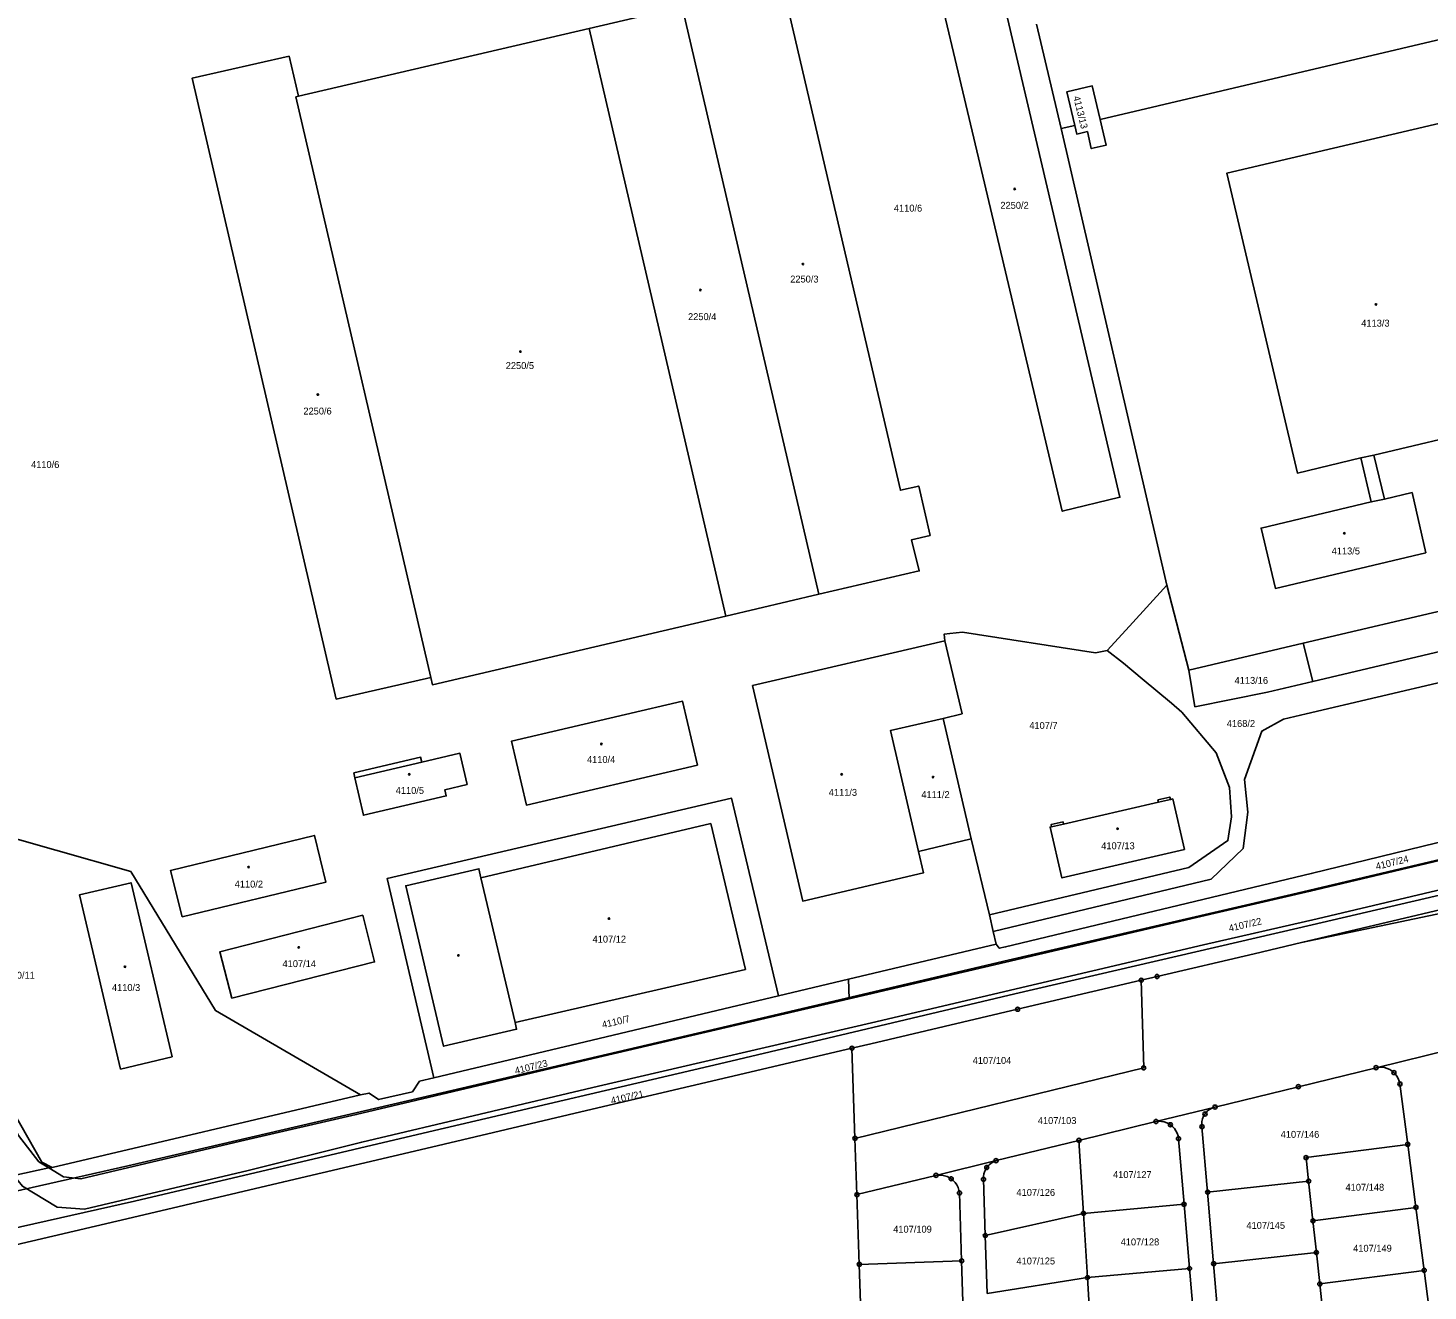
# Model space of a CAD drawing. Extents: x -733394 to -722299, y -1082822 to -1075049.
# Drawn here: x -728180.6 to -727836.8, y -1080927.6 to -1080617.4 of the extents above; entities that cross this region are included whole.
import ezdxf

# ---------------------------------------------------------------- set-up
doc = ezdxf.new("R2010")
doc.units = 0
for name, color, linetype in [('Hranice parcel', 7, 'Continuous'), ('Parcelní čísla', 7, 'Continuous'), ('Vnitřní kresba', 7, 'Continuous'), ('Značky bodu BP', 7, 'Continuous'), ('Značky budov', 7, 'Continuous')]:
    doc.layers.add(name, color=color, linetype=linetype)

msp = doc.modelspace()

# ---------------------------------------------------------------- linework, layer by layer
at = {"layer": 'Hranice parcel'}
for p, q in [((-728019.93, -1080612.18), (-728042.79, -1080617.52)), ((-728019.93, -1080612.18), (-727986.32, -1080756.51)), ((-727932.89, -1080616.46), (-727926.83, -1080642.13)), ((-727917.27, -1080639.88), (-727812.13, -1080615.13)), ((-728042.79, -1080617.52), (-728114.15, -1080634.19)), ((-728042.79, -1080617.52), (-728009.18, -1080761.86)), ((-727926.83, -1080642.13), (-727923.52, -1080641.35)), ((-727926.83, -1080642.13), (-727900.86, -1080754.24)), ((-727853.28, -1080722.98), (-727850.06, -1080722.32)), ((-727781.26, -1080748.19), (-727867.44, -1080768.52)), ((-727900.86, -1080754.24), (-727895.51, -1080775.14)), ((-728009.18, -1080761.86), (-727986.32, -1080756.51)), ((-727865.08, -1080777.91), (-727767.33, -1080754.84)), ((-727867.44, -1080768.52), (-727895.51, -1080775.14)), ((-727865.08, -1080777.91), (-727867.44, -1080768.52)), ((-727955.78, -1080786.98), (-727948.92, -1080816.58)), ((-727867.8, -1080842.03), (-727745.31, -1080813.05)), ((-727961.84, -1080819.67), (-727948.92, -1080816.58)), ((-727948.92, -1080816.58), (-727944.46, -1080835.28)), ((-727944.46, -1080835.28), (-727943.51, -1080839.35)), ((-727943.51, -1080839.35), (-727942.78, -1080842.47)), ((-727942.78, -1080842.47), (-727979.06, -1080851.08)), ((-727979.06, -1080851.08), (-727996.25, -1080855.17)), ((-727978.89, -1080855.88), (-727979.06, -1080851.08)), ((-727996.25, -1080855.17), (-728080.91, -1080875.25)), ((-727977.47, -1080890.16), (-727978.23, -1080868)), ((-727830.91, -1080868.23), (-727849.52, -1080872.78)), ((-727843.66, -1080876.78), (-727841.73, -1080891.63)), ((-728098.92, -1080879.42), (-728174.61, -1080897.33)), ((-727889.05, -1080882.45), (-727903.58, -1080886.01)), ((-727922.47, -1080890.63), (-727903.58, -1080886.01)), ((-727890.89, -1080903.36), (-727892.26, -1080887.28)), ((-727977, -1080903.97), (-727977.47, -1080890.16)), ((-727942.84, -1080895.62), (-727922.47, -1080890.63)), ((-727921.36, -1080908.58), (-727922.47, -1080890.63)), ((-727898.03, -1080890.23), (-727896.66, -1080906.34)), ((-727841.73, -1080891.63), (-727839.72, -1080907.1)), ((-728184, -1080899.3), (-728175.41, -1080897.39)), ((-728175.41, -1080897.39), (-728174.61, -1080897.33)), ((-727942.84, -1080895.62), (-727957.6, -1080899.23)), ((-727977, -1080903.97), (-727957.6, -1080899.23)), ((-727945.48, -1080913.99), (-727945.91, -1080900.2)), ((-727866.07, -1080900.66), (-727890.89, -1080903.36)), ((-727865.02, -1080910.4), (-727866.07, -1080900.66)), ((-727976.41, -1080921.1), (-727977, -1080903.97)), ((-727951.81, -1080903.56), (-727951.28, -1080920.23)), ((-727889.4, -1080920.93), (-727890.89, -1080903.36)), ((-727921.36, -1080908.58), (-727945.48, -1080913.99)), ((-727921.36, -1080908.58), (-727896.66, -1080906.34)), ((-727920.39, -1080924.33), (-727921.36, -1080908.58)), ((-727896.66, -1080906.34), (-727895.32, -1080922.11)), ((-727865.02, -1080910.4), (-727839.72, -1080907.1)), ((-727839.72, -1080907.1), (-727837.7, -1080922.57)), ((-727864.17, -1080918.18), (-727865.02, -1080910.4)), ((-727945.02, -1080928.26), (-727945.48, -1080913.99)), ((-727864.17, -1080918.18), (-727889.4, -1080920.93)), ((-727863.33, -1080925.91), (-727864.17, -1080918.18)), ((-727976.41, -1080921.1), (-727951.28, -1080920.23)), ((-727975.83, -1080938.05), (-727976.41, -1080921.1)), ((-727951.28, -1080920.23), (-727950.74, -1080937.18)), ((-727920.39, -1080924.33), (-727895.32, -1080922.11)), ((-727895.32, -1080922.11), (-727893.98, -1080937.88)), ((-727887.91, -1080938.51), (-727889.4, -1080920.93)), ((-727863.33, -1080925.91), (-727837.7, -1080922.57)), ((-727837.7, -1080922.57), (-727835.69, -1080938.04)), ((-727920.39, -1080924.33), (-727945.02, -1080928.26)), ((-727919.41, -1080940.12), (-727920.39, -1080924.33)), ((-727862.26, -1080935.72), (-727863.33, -1080925.91))]:
    msp.add_line(p, q, dxfattribs=at)
for points in [[(-727947.15, -1080584.43), (-727947.53, -1080584.52), (-727961.69, -1080587.81), (-727946.42, -1080652.42), (-727926.58, -1080736.12), (-727912.4, -1080732.68), (-727933.04, -1080644.64), (-727945.39, -1080591.93)], [(-727986.32, -1080756.51), (-727961.69, -1080750.75), (-727963.56, -1080743.13), (-727959.05, -1080742.05), (-727961.81, -1080729.91), (-727966.3, -1080730.96), (-727998.03, -1080594.76), (-728022.67, -1080600.43), (-728019.93, -1080612.18)], [(-728114.15, -1080634.19), (-728116.44, -1080624.34), (-728140.28, -1080629.76), (-728104.86, -1080782.23), (-728081.64, -1080776.93)], [(-727923.52, -1080641.35), (-727925.46, -1080633.11), (-727919.2, -1080631.64), (-727917.27, -1080639.88)], [(-728114.15, -1080634.19), (-728114.78, -1080634.34), (-728081.64, -1080776.93)], [(-727850.06, -1080722.32), (-727822.47, -1080715.82), (-727821.94, -1080718.07), (-727816.08, -1080716.69), (-727816.61, -1080714.44), (-727812.6, -1080713.5), (-727812.75, -1080712.87), (-727801.99, -1080710.37), (-727805.52, -1080695.23), (-727809.94, -1080696.23), (-727813.81, -1080679.78), (-727820.19, -1080681.28), (-727825.02, -1080660.74), (-727820.16, -1080659.59), (-727825.36, -1080637.37), (-727830.23, -1080638.64), (-727829.94, -1080639.86), (-727886.16, -1080653.1), (-727868.82, -1080726.74), (-727853.28, -1080722.98)], [(-727923.52, -1080641.35), (-727923.02, -1080643.47), (-727920.38, -1080642.86), (-727919.44, -1080647.02), (-727915.79, -1080646.16), (-727916.77, -1080642), (-727917.27, -1080639.88)], [(-727853.28, -1080722.98), (-727850.7, -1080733.83), (-727877.73, -1080740.25), (-727874.21, -1080755.07), (-727837.3, -1080746.31), (-727840.66, -1080731.53), (-727847.48, -1080733.17), (-727850.06, -1080722.32)], [(-727900.86, -1080754.24), (-727910.06, -1080764.31), (-727915.54, -1080770.32)], [(-728081.64, -1080776.93), (-728081.23, -1080778.72), (-728009.18, -1080761.86)], [(-727955.4, -1080767.96), (-728002.62, -1080778.94), (-727990.32, -1080831.86), (-727960.63, -1080824.9), (-727961.84, -1080819.67)], [(-727955.4, -1080767.96), (-727951.19, -1080785.84), (-727955.78, -1080786.98)], [(-727915.54, -1080770.32), (-727918.39, -1080770.88), (-727951.07, -1080765.85), (-727954.16, -1080766.1), (-727955.55, -1080766.29), (-727955.4, -1080767.96)], [(-727944.46, -1080835.28), (-727895.46, -1080823.63), (-727885.89, -1080817), (-727885.02, -1080811.18), (-727885.53, -1080803.98), (-727888.81, -1080795.47), (-727897.23, -1080785.47), (-727899.73, -1080783.24), (-727906.96, -1080777.29), (-727911.5, -1080773.42), (-727915.54, -1080770.32)], [(-727814.39, -1080773.56), (-727866.68, -1080785.89), (-727872.28, -1080787.15), (-727877.59, -1080790.1), (-727881.84, -1080802.02), (-727880.98, -1080810.03), (-727882.12, -1080818.91), (-727890.03, -1080826.44), (-727943.51, -1080839.35)], [(-727895.51, -1080775.14), (-727893.99, -1080784.12), (-727876.15, -1080780.52), (-727865.08, -1080777.91)], [(-728016.16, -1080798.47), (-728019.83, -1080782.76), (-728061.83, -1080792.59), (-728058.15, -1080808.29), (-728016.16, -1080798.47)], [(-728098.92, -1080879.42), (-728134.47, -1080858.77), (-728155.31, -1080824.56), (-728210.64, -1080808.91), (-728216.54, -1080785.94), (-728226.14, -1080788.18)], [(-727955.78, -1080786.98), (-727968.74, -1080789.95), (-727961.84, -1080819.67)], [(-728100.58, -1080800.39), (-728100.3, -1080801.58), (-728098.19, -1080810.79), (-728077.86, -1080806.03), (-728078.18, -1080804.5), (-728072.71, -1080803.22), (-728074.48, -1080795.57), (-728083.86, -1080797.74), (-728084.14, -1080796.55), (-728100.58, -1080800.39)], [(-727749.55, -1080798.16), (-727755.62, -1080803.45), (-727790.2, -1080811.62), (-727819.45, -1080818.49), (-727865.68, -1080829.44), (-727893.59, -1080835.91), (-727974.35, -1080854.82), (-727978.89, -1080855.88)], [(-727942.78, -1080842.47), (-727942.04, -1080843.43), (-727940.49, -1080843.12), (-727865.45, -1080825.12), (-727800.37, -1080809.2), (-727774.19, -1080802.88), (-727765.03, -1080801.44), (-727763.22, -1080801.08), (-727752.53, -1080797.28)], [(-727996.25, -1080855.17), (-728007.79, -1080806.59), (-728092.35, -1080826.3), (-728080.91, -1080875.25)], [(-727929.18, -1080813.62), (-727929.3, -1080813.09), (-727926.39, -1080812.41), (-727926.26, -1080812.95), (-727902.95, -1080807.53), (-727903.07, -1080807), (-727900.16, -1080806.32), (-727900.02, -1080806.9), (-727899.46, -1080806.77), (-727896.59, -1080819.17), (-727926.65, -1080826.16), (-727929.58, -1080813.69), (-727929.18, -1080813.62)], [(-727745.76, -1080812.22), (-727755.74, -1080810.75), (-727788.19, -1080818.35), (-727817.68, -1080825.26), (-727864.01, -1080836.21), (-727891.86, -1080842.59), (-727973.43, -1080861.79), (-728040.43, -1080877.34), (-728098.59, -1080891.05), (-728126.45, -1080898.03), (-728166.69, -1080907.55), (-728173.37, -1080907.05), (-728181.94, -1080901.9), (-728184, -1080899.3)], [(-728060.94, -1080861.7), (-728004.38, -1080848.64), (-728012.88, -1080812.83), (-728069.32, -1080826.16), (-728069.84, -1080823.91), (-728087.79, -1080828.08), (-728078.5, -1080867.52), (-728060.56, -1080863.35), (-728060.94, -1080861.7)], [(-728142.68, -1080835.73), (-728107.42, -1080827.24), (-728110.2, -1080815.75), (-728145.56, -1080824.31), (-728142.68, -1080835.73)], [(-728157.82, -1080873.15), (-728145.19, -1080870.1), (-728155.25, -1080827.35), (-728167.88, -1080830.32), (-728157.82, -1080873.15)], [(-728098.35, -1080835.36), (-728133.46, -1080844.29), (-728130.48, -1080855.7), (-728095.44, -1080846.81), (-728098.35, -1080835.36)], [(-727867.8, -1080842.03), (-727833.01, -1080834.74), (-727830.21, -1080834.07)], [(-727907.17, -1080851.3), (-727903.28, -1080850.39), (-727879.48, -1080844.79), (-727867.8, -1080842.03)], [(-727978.23, -1080868), (-727973.62, -1080866.92), (-727937.54, -1080858.44), (-727907.17, -1080851.3)], [(-727907.17, -1080851.3), (-727906.56, -1080872.81), (-727977.47, -1080890.16)], [(-728174.61, -1080897.33), (-728177.16, -1080895.95), (-728200.2, -1080855.48), (-728211.86, -1080858.31)], [(-727978.89, -1080855.88), (-728041.74, -1080870.53), (-728099.96, -1080884.32), (-728128.38, -1080890.87), (-728167.57, -1080900.11), (-728171.82, -1080899.59), (-728175.41, -1080897.39)], [(-728175.41, -1080897.39), (-728177.87, -1080895.89), (-728182.9, -1080889.44), (-728193.29, -1080869.36), (-728201.6, -1080861.45), (-728212.6, -1080859.39)], [(-727978.23, -1080868), (-728008.57, -1080875.14), (-728044.79, -1080883.65), (-728081.44, -1080892.27), (-728117.77, -1080900.81), (-728153.52, -1080909.22), (-728190.25, -1080917.85), (-728197.94, -1080919.66)], [(-727889.05, -1080882.45), (-727868.6, -1080877.45), (-727849.52, -1080872.78)], [(-727849.52, -1080872.78), (-727848.83, -1080872.68), (-727848.14, -1080872.67), (-727847.45, -1080872.77), (-727846.78, -1080872.96), (-727846.14, -1080873.25), (-727845.89, -1080873.4), (-727845.33, -1080873.81), (-727844.83, -1080874.29), (-727844.41, -1080874.84), (-727844.06, -1080875.45), (-727843.81, -1080876.1), (-727843.66, -1080876.78)], [(-728080.91, -1080875.25), (-728084.39, -1080876.09), (-728086.15, -1080878.69), (-728094.48, -1080880.62), (-728096.78, -1080879.03), (-728098.92, -1080879.42)], [(-727892.26, -1080887.28), (-727892.31, -1080886.63), (-727892.26, -1080885.97), (-727892.11, -1080885.33), (-727891.87, -1080884.73), (-727891.65, -1080884.32), (-727891.25, -1080883.8), (-727890.79, -1080883.34), (-727890.26, -1080882.95), (-727889.67, -1080882.66), (-727889.05, -1080882.45)], [(-727903.58, -1080886.01), (-727902.9, -1080885.94), (-727902.21, -1080885.97), (-727901.53, -1080886.09), (-727900.88, -1080886.32), (-727900.27, -1080886.64), (-727900.05, -1080886.78), (-727899.52, -1080887.21), (-727899.05, -1080887.71), (-727898.66, -1080888.28), (-727898.35, -1080888.9), (-727898.14, -1080889.55), (-727898.03, -1080890.23)], [(-727866.07, -1080900.66), (-727866.7, -1080894.88), (-727841.73, -1080891.63)], [(-727945.91, -1080900.2), (-727945.91, -1080899.53), (-727945.82, -1080898.87), (-727945.62, -1080898.24), (-727945.36, -1080897.68), (-727944.99, -1080897.13), (-727944.55, -1080896.63), (-727944.03, -1080896.21), (-727943.46, -1080895.87), (-727942.84, -1080895.62)], [(-727957.6, -1080899.23), (-727956.9, -1080899.16), (-727956.2, -1080899.18), (-727955.51, -1080899.31), (-727954.84, -1080899.53), (-727954.21, -1080899.84), (-727953.91, -1080900.04), (-727953.36, -1080900.48), (-727952.88, -1080901), (-727952.48, -1080901.57), (-727952.16, -1080902.2), (-727951.94, -1080902.87), (-727951.81, -1080903.56)]]:
    msp.add_lwpolyline(points, dxfattribs=at)
at = {"layer": 'Vnitřní kresba'}
for p, q in [((-727850.7, -1080733.83), (-727847.48, -1080733.17)), ((-728100.3, -1080801.58), (-728083.86, -1080797.74)), ((-727902.95, -1080807.53), (-727900.02, -1080806.9)), ((-727929.18, -1080813.62), (-727926.26, -1080812.95)), ((-727870.32, -1080830.22), (-727799.05, -1080813.45)), ((-727868.72, -1080838.5), (-727797.3, -1080821.91)), ((-728069.32, -1080826.16), (-728060.94, -1080861.7)), ((-727870.32, -1080830.22), (-727939.85, -1080846.39)), ((-727938.18, -1080854.66), (-727868.72, -1080838.5)), ((-728011.22, -1080863.17), (-727939.85, -1080846.39)), ((-728009.33, -1080871.55), (-727938.18, -1080854.66)), ((-728083.81, -1080880.08), (-728011.22, -1080863.17)), ((-728082.16, -1080888.54), (-728009.33, -1080871.55)), ((-728156.05, -1080896.88), (-728083.81, -1080880.08)), ((-728154.42, -1080905.58), (-728082.16, -1080888.54)), ((-728192.47, -1080905.09), (-728156.05, -1080896.88)), ((-728191.14, -1080913.82), (-728154.42, -1080905.58))]:
    msp.add_line(p, q, dxfattribs=at)
at = {"layer": 'Značky bodu BP'}
for centre, radius in [((-727903.28, -1080850.39), 0.5), ((-727903.28, -1080850.39), 0.0303), ((-727907.17, -1080851.3), 0.5), ((-727907.17, -1080851.3), 0.0303), ((-727937.54, -1080858.44), 0.5), ((-727937.54, -1080858.44), 0.0303), ((-727978.23, -1080868), 0.5), ((-727978.23, -1080868), 0.0303), ((-727906.56, -1080872.81), 0.5), ((-727906.56, -1080872.81), 0.0303), ((-727849.52, -1080872.78), 0.5), ((-727849.52, -1080872.78), 0.0303), ((-727845.12, -1080873.99), 0.5), ((-727845.12, -1080873.99), 0.0303), ((-727868.6, -1080877.45), 0.5), ((-727868.6, -1080877.45), 0.0303), ((-727843.66, -1080876.78), 0.5), ((-727843.66, -1080876.78), 0.0303), ((-727891.53, -1080884.15), 0.5), ((-727891.53, -1080884.15), 0.0303), ((-727889.05, -1080882.45), 0.5), ((-727889.05, -1080882.45), 0.0303), ((-727903.58, -1080886.01), 0.5), ((-727903.58, -1080886.01), 0.0303), ((-727900.02, -1080886.8), 0.5), ((-727900.02, -1080886.8), 0.0303), ((-727892.26, -1080887.28), 0.5), ((-727892.26, -1080887.28), 0.0303), ((-727977.47, -1080890.16), 0.5), ((-727977.47, -1080890.16), 0.0303), ((-727922.47, -1080890.63), 0.5), ((-727922.47, -1080890.63), 0.0303), ((-727898.03, -1080890.23), 0.5), ((-727898.03, -1080890.23), 0.0303), ((-727841.73, -1080891.63), 0.5), ((-727841.73, -1080891.63), 0.0303), ((-727942.84, -1080895.62), 0.5), ((-727866.7, -1080894.88), 0.5), ((-727866.7, -1080894.88), 0.0303), ((-727957.6, -1080899.23), 0.5), ((-727945.12, -1080897.3), 0.5), ((-727945.12, -1080897.3), 0.0303), ((-727942.84, -1080895.62), 0.0303), ((-727957.6, -1080899.23), 0.0303), ((-727953.86, -1080900.07), 0.5), ((-727953.86, -1080900.07), 0.0303), ((-727945.91, -1080900.2), 0.5), ((-727945.91, -1080900.2), 0.0303), ((-727866.07, -1080900.66), 0.5), ((-727866.07, -1080900.66), 0.0303), ((-727977, -1080903.97), 0.5), ((-727977, -1080903.97), 0.0303), ((-727951.81, -1080903.56), 0.5), ((-727951.81, -1080903.56), 0.0303), ((-727890.89, -1080903.36), 0.5), ((-727890.89, -1080903.36), 0.0303), ((-727921.36, -1080908.58), 0.5), ((-727921.36, -1080908.58), 0.0303), ((-727896.66, -1080906.34), 0.5), ((-727896.66, -1080906.34), 0.0303), ((-727839.72, -1080907.1), 0.5), ((-727839.72, -1080907.1), 0.0303), ((-727865.02, -1080910.4), 0.5), ((-727865.02, -1080910.4), 0.0303), ((-727945.48, -1080913.99), 0.5), ((-727945.48, -1080913.99), 0.0303), ((-727864.17, -1080918.18), 0.5), ((-727864.17, -1080918.18), 0.0303), ((-727976.41, -1080921.1), 0.5), ((-727976.41, -1080921.1), 0.0303), ((-727951.28, -1080920.23), 0.5), ((-727951.28, -1080920.23), 0.0303), ((-727895.32, -1080922.11), 0.5), ((-727895.32, -1080922.11), 0.0303), ((-727889.4, -1080920.93), 0.5), ((-727889.4, -1080920.93), 0.0303), ((-727837.7, -1080922.57), 0.5), ((-727837.7, -1080922.57), 0.0303), ((-727920.39, -1080924.33), 0.5), ((-727920.39, -1080924.33), 0.0303), ((-727863.33, -1080925.91), 0.5), ((-727863.33, -1080925.91), 0.0303)]:
    msp.add_circle(centre, radius, dxfattribs=at)
at = {"layer": 'Značky budov'}
for centre in [(-727938.26, -1080656.96), (-727990.26, -1080675.4), (-728015.43, -1080681.77), (-727849.54, -1080685.32), (-728059.64, -1080696.88), (-728109.38, -1080707.45), (-727857.3, -1080741.52), (-728039.74, -1080793.28), (-728086.95, -1080800.73), (-727980.74, -1080800.72), (-727958.28, -1080801.41), (-727913, -1080814.1), (-728126.4, -1080823.52), (-728037.88, -1080836.15), (-728114.07, -1080843.25), (-728074.85, -1080845.2), (-728156.74, -1080847.99)]:
    msp.add_circle(centre, 0.175, dxfattribs=at)

# ---------------------------------------------------------------- texts
at = {"layer": 'Parcelní čísla'}
for s, rotation, p in [('4113/13', 284, (-727923.9, -1080634.33)), ('4107/24', 14, (-727849.37, -1080824.22)), ('4107/22', 13, (-727885.49, -1080839.41)), ('4110/7', 13, (-728039.41, -1080863.09)), ('4107/23', 14, (-728060.79, -1080874.41)), ('4107/21', 13, (-728037.23, -1080881.77))]:
    msp.add_text(s, height=1.7, rotation=rotation, dxfattribs=at).set_placement(p)
for s, p in [('4110/6', (-727967.93, -1080662.52)), ('2250/2', (-727941.77, -1080661.82)), ('2250/3', (-727993.38, -1080679.93)), ('2250/4', (-728018.47, -1080689.17)), ('4113/3', (-727853.15, -1080690.76)), ('2250/5', (-728063.24, -1080701.18)), ('2250/6', (-728112.93, -1080712.35)), ('4110/6', (-728179.81, -1080725.5)), ('4113/5', (-727860.42, -1080746.72)), ('4113/16', (-727884.25, -1080778.5)), ('4107/7', (-727934.67, -1080789.59)), ('4168/2', (-727886.17, -1080789.09)), ('4110/4', (-728043.29, -1080797.95)), ('4110/5', (-728090.26, -1080805.53)), ('4111/3', (-727983.92, -1080806.01)), ('4111/2', (-727961.18, -1080806.56)), ('4107/13', (-727917, -1080819.13)), ('4110/2', (-728129.8, -1080828.54)), ('4107/12', (-728041.91, -1080842.06)), ('4107/14', (-728118.05, -1080848.08)), ('4110/11', (-728187.1, -1080850.93)), ('4110/3', (-728159.95, -1080853.96)), ('4107/104', (-727948.57, -1080871.85)), ('4107/103', (-727932.58, -1080886.62)), ('4107/146', (-727872.94, -1080890.01)), ('4107/127', (-727914.11, -1080899.89)), ('4107/148', (-727857.01, -1080903.01)), ('4107/126', (-727937.82, -1080904.26)), ('4107/109', (-727968.09, -1080913.31)), ('4107/145', (-727881.35, -1080912.37)), ('4107/128', (-727912.24, -1080916.43)), ('4107/125', (-727937.82, -1080921.11)), ('4107/149', (-727855.14, -1080917.99))]:
    msp.add_text(s, height=1.7, dxfattribs=at).set_placement(p)

doc.saveas('drawing.dxf')
